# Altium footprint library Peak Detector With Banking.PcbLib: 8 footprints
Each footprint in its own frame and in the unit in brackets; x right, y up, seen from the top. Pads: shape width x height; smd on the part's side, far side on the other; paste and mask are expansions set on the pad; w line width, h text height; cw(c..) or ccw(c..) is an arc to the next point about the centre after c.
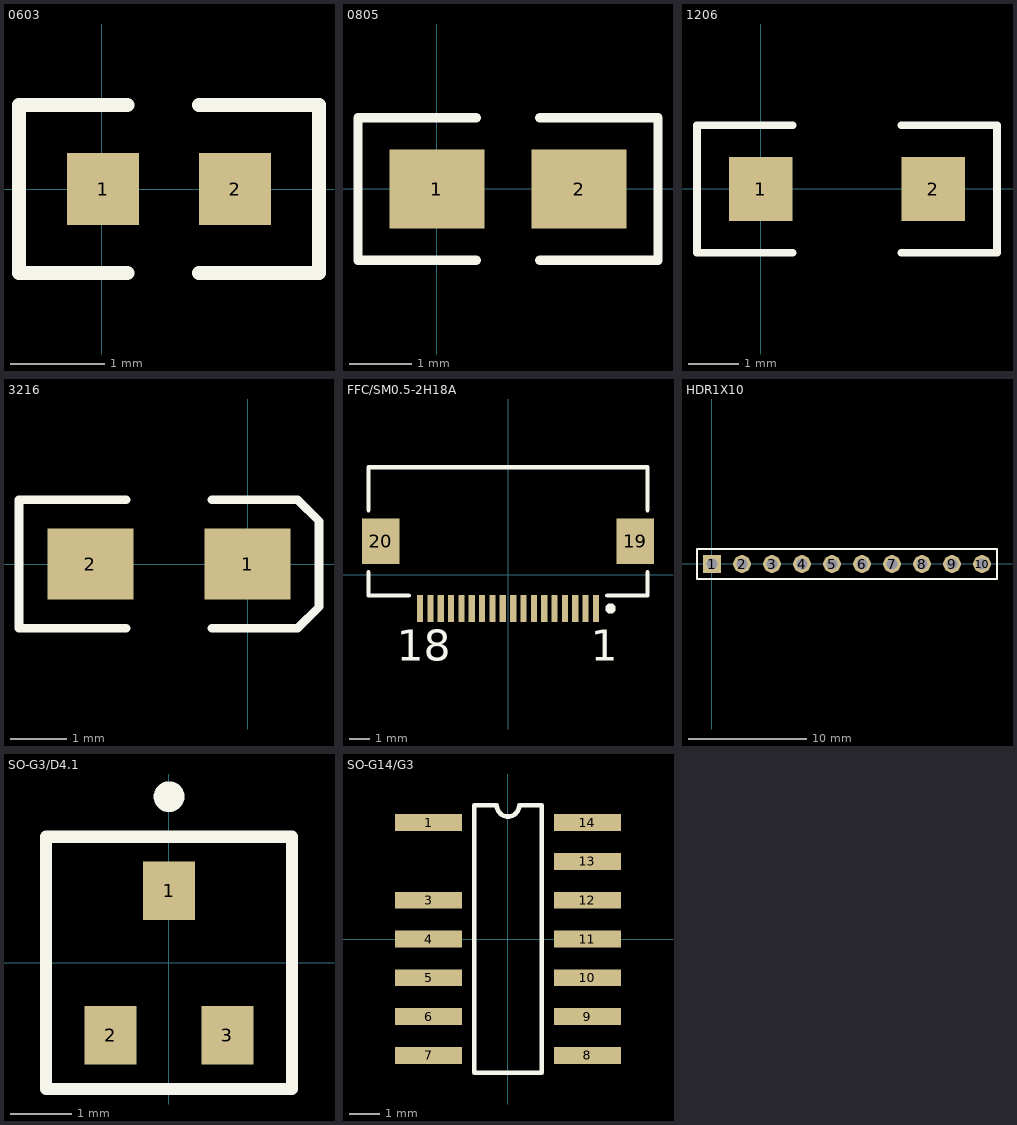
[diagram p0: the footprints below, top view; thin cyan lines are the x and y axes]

## 0603 [mil]
pads (2):
  rect 30x30 smd: 1(0.43,0) 2(55.43,0)
Top Overlay:
  lines w6: -34.58,-35 10.44,-35 ; -34.58,35 10.44,35 ; -34.57,-35 -34.57,35 ; 40.43,-35 90.43,-35 90.43,35 40.43,35

## 0805 [mil]
pads (2):
  rect 60x50 smd: 1(0.01,0) 2(90.01,0)
Top Overlay:
  lines w6: 25.01,-45 -49.99,-45 -49.99,45 25.01,45 ; 65.01,-45 140.01,-45 140.01,45 65.01,45

## 1206 [mil]
pads (2):
  rect 50x50 smd: 1(0,0) 2(135,0)
Top Overlay:
  lines w6: 25,-50 -50,-50 -50,50 25,50 ; 110,-50 185,-50 185,50 110,50

## 3216 [mil]
pads (2):
  rect 60x50 smd: 1(0.01,0) 2(-109.99,0)
Top Overlay:
  lines w6: -84.99,-45 -159.99,-45 -159.99,45 -84.99,45 ; -24.99,-45 35.01,-45 50.01,-30 50.01,30 35.01,45 -24.99,45

## FFC/SM0.5-2H18A [mm]
pads (20):
  rect 0.3x1.3 smd: 1(4.25,-1.625) 2(3.75,-1.625) 3(3.25,-1.625) 4(2.75,-1.625) 5(2.25,-1.625) 6(1.75,-1.625) 7(1.25,-1.625) 8(0.75,-1.625) 9(0.25,-1.625) 10(-0.25,-1.625) 11(-0.75,-1.625) 12(-1.25,-1.625) 13(-1.75,-1.625) 14(-2.25,-1.625) 15(-2.75,-1.625) 16(-3.25,-1.625) 17(-3.75,-1.625) 18(-4.25,-1.625)
  rect 1.8x2.2 smd: 19(6.15,1.625) 20(-6.15,1.625)
Top Overlay:
  circle w0.25: c4.95,-1.625 r0.125
  lines w0.2: -6.75,0.125 -6.75,-1 -4.8,-1 ; -6.75,3.125 -6.75,5.2 6.75,5.2 6.75,3.125 ; 4.8,-1 6.75,-1 6.75,0.125
  text "18" at -5.375,-4.15 h1.5
  text "1" at 4,-4.15 h1.5

## HDR1X10 [mm]
pads (10):
  rect 1.5x1.5 hole 0.9: 1(0,0)
  round 1.5 hole 0.9: 2(2.54,0) 3(5.08,0) 4(7.62,0) 5(10.16,0) 6(12.7,0) 7(15.24,0) 8(17.78,0) 9(20.32,0) 10(22.86,0)
Top Overlay:
  lines w0.2: -1.27,-1.27 -1.27,1.27 0.635,1.27 24.13,1.27 24.13,-1.27 -1.27,-1.27

## SO-G3/D4.1 [mm]
pads (3):
  rect 0.85x0.95 smd: 1(0,1.175) 2(-0.95,-1.175) 3(0.95,-1.175)
Top Overlay:
  circle w0.25: c0,2.7 r0.125
  lines w0.2: -2,-2.05 -2,2.05 2,2.05 2,-2.05 -2,-2.05

## SO-G14/G3 [mm]
pads (13):
  rect 2.2x0.55 smd: 1(-2.6,3.81) 3(-2.6,1.27) 4(-2.6,0) 5(-2.6,-1.27) 6(-2.6,-2.54) 7(-2.6,-3.81) 8(2.6,-3.81) 9(2.6,-2.54) 10(2.6,-1.27) 11(2.6,0) 12(2.6,1.27) 13(2.6,2.54) 14(2.6,3.81)
Top Overlay:
  lines w0.152: -1.1,-4.375 1.1,-4.375 1.1,4.375 0.367,4.375 cw(c0,4.375) -0.366,4.375 -1.1,4.375 -1.1,-4.375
